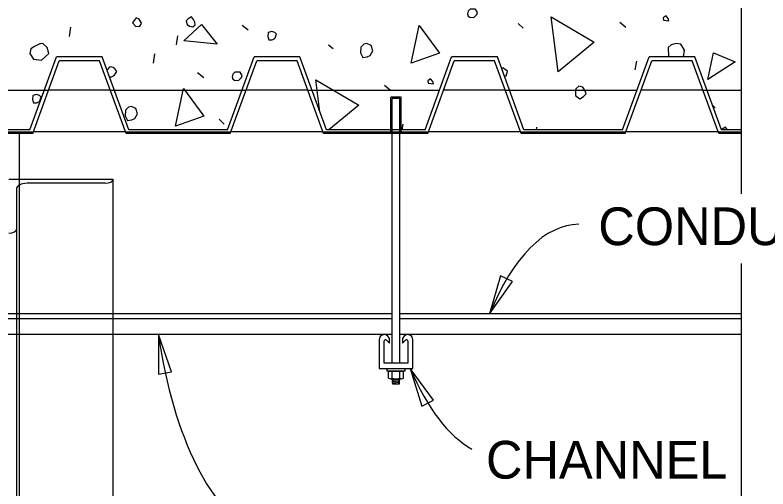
# Model space of a CAD drawing. Extents: x -1660015.2 to -1659984.9, y 2580594.2 to 2580616.7.
# Drawn here: x -1659997.457 to -1659994.444, y 2580601.617 to 2580603.515 of the extents above; entities that cross this region are included whole.
import ezdxf

# ---------------------------------------------------------------- set-up
doc = ezdxf.new("R2010")
doc.units = 0
for name, color, linetype in [('Default', 7, 'Continuous'), ('Miscellaneous', 7, 'Continuous'), ('PlotBorder_dp', 7, 'Continuous'), ('SheetLines_dp', 7, 'Continuous'), ('SteelGirder', 7, 'Continuous')]:
    doc.layers.add(name, color=color, linetype=linetype)

msp = doc.modelspace()

# ---------------------------------------------------------------- linework, layer by layer
at = {"layer": 'Default'}
for p, q in [((-1659997.8661, 2580603.2146), (-1659997.3226, 2580603.2146)), ((-1659997.0757, 2580603.2146), (-1659996.5322, 2580603.2146)), ((-1659996.2852, 2580603.2146), (-1659995.7583, 2580603.2146)), ((-1659995.4948, 2580603.2146), (-1659994.9679, 2580603.2146)), ((-1659994.7044, 2580603.2146), (-1659994.5491, 2580603.2146)), ((-1659997.8054, 2580603.0479), (-1659997.3833, 2580603.0479)), ((-1659997.015, 2580603.0479), (-1659996.5928, 2580603.0479)), ((-1659996.2246, 2580603.0479), (-1659996.1516, 2580603.0479)), ((-1659996.2246, 2580603.0479), (-1659995.8024, 2580603.0479)), ((-1659995.4341, 2580603.0479), (-1659995.3612, 2580603.0479)), ((-1659995.4341, 2580603.0479), (-1659995.012, 2580603.0479)), ((-1659994.6437, 2580603.0479), (-1659994.5707, 2580603.0479)), ((-1659994.6437, 2580603.0479), (-1659994.5491, 2580603.0479)), ((-1659997.4398, 2580602.8574), (-1659997.4398, 2580597.9633)), ((-1659997.0649, 2580602.3186), (-1659997.6586, 2580602.3186)), ((-1659995.9478, 2580602.3186), (-1659997.0649, 2580602.3186)), ((-1659994.5491, 2580602.3186), (-1659995.9166, 2580602.3186)), ((-1659997.0649, 2580602.2978), (-1659997.6586, 2580602.2978)), ((-1659995.9478, 2580602.2978), (-1659997.0649, 2580602.2978)), ((-1659994.5491, 2580602.2978), (-1659995.9166, 2580602.2978)), ((-1659997.0649, 2580602.2353), (-1659997.6586, 2580602.2353)), ((-1659995.9478, 2580602.2353), (-1659997.0649, 2580602.2353)), ((-1659995.9583, 2580602.2194), (-1659995.9605, 2580602.2237)), ((-1659994.5491, 2580602.2353), (-1659995.9166, 2580602.2353)), ((-1659995.904, 2580602.2237), (-1659995.9061, 2580602.2194)), ((-1659995.9999, 2580602.2145), (-1659995.9999, 2580602.0999)), ((-1659995.9791, 2580602.1207), (-1659995.9791, 2580602.2097)), ((-1659995.9703, 2580602.2134), (-1659995.9583, 2580602.2015)), ((-1659995.9583, 2580602.2015), (-1659995.9583, 2580602.2194)), ((-1659995.9061, 2580602.2194), (-1659995.9061, 2580602.2015)), ((-1659995.9061, 2580602.2015), (-1659995.8942, 2580602.2134)), ((-1659995.8853, 2580602.2097), (-1659995.8853, 2580602.1207)), ((-1659995.8645, 2580602.0999), (-1659995.8645, 2580602.2145)), ((-1659995.8853, 2580602.1207), (-1659995.9791, 2580602.1207)), ((-1659995.9999, 2580602.0999), (-1659995.8645, 2580602.0999))]:
    msp.add_line(p, q, dxfattribs=at)
for centre, radius, start, end in [((-1659995.9791, 2580602.2145), 0.0208, 26.1794, 179.9999), ((-1659995.8853, 2580602.2145), 0.0208, 0.0001, 153.8206), ((-1659995.9739, 2580602.2097), 0.0052, 45, 180), ((-1659995.8905, 2580602.2097), 0.0052, 360, 135)]:
    msp.add_arc(centre, radius, start, end, dxfattribs=at)
at = {"layer": 'Miscellaneous'}
for p, q in [((-1659997.239, 2580603.4291), (-1659997.2336, 2580603.4668)), ((-1659996.5472, 2580603.4747), (-1659996.5239, 2580603.4551)), ((-1659995.4436, 2580603.4805), (-1659995.4233, 2580603.4627)), ((-1659995.0362, 2580603.4861), (-1659995.0129, 2580603.4665)), ((-1659996.8109, 2580603.3963), (-1659996.8049, 2580603.4315)), ((-1659996.2027, 2580603.3962), (-1659996.183, 2580603.3807)), ((-1659997.397, 2580603.0559), (-1659997.2908, 2580603.3477)), ((-1659997.1075, 2580603.3477), (-1659997.2908, 2580603.3477)), ((-1659997.0013, 2580603.0559), (-1659997.1075, 2580603.3477)), ((-1659996.9025, 2580603.3225), (-1659996.897, 2580603.3602)), ((-1659996.6065, 2580603.0559), (-1659996.5004, 2580603.3477)), ((-1659996.3171, 2580603.3477), (-1659996.5004, 2580603.3477)), ((-1659996.2109, 2580603.0559), (-1659996.3171, 2580603.3477)), ((-1659995.8161, 2580603.0559), (-1659995.7099, 2580603.3477)), ((-1659995.5266, 2580603.3477), (-1659995.7099, 2580603.3477)), ((-1659995.6986, 2580603.3501), (-1659995.6961, 2580603.3477)), ((-1659995.4204, 2580603.0559), (-1659995.5266, 2580603.3477)), ((-1659995.0257, 2580603.0559), (-1659994.9195, 2580603.3477)), ((-1659994.7362, 2580603.3477), (-1659994.9195, 2580603.3477)), ((-1659994.63, 2580603.0559), (-1659994.7362, 2580603.3477)), ((-1659997.3861, 2580603.0403), (-1659997.2799, 2580603.3321)), ((-1659997.1184, 2580603.3321), (-1659997.2799, 2580603.3321)), ((-1659997.0122, 2580603.0403), (-1659997.1184, 2580603.3321)), ((-1659996.5956, 2580603.0403), (-1659996.4894, 2580603.3321)), ((-1659996.328, 2580603.3321), (-1659996.4894, 2580603.3321)), ((-1659996.2218, 2580603.0403), (-1659996.328, 2580603.3321)), ((-1659995.8052, 2580603.0403), (-1659995.699, 2580603.3321)), ((-1659995.5375, 2580603.3321), (-1659995.699, 2580603.3321)), ((-1659995.4313, 2580603.0403), (-1659995.5375, 2580603.3321)), ((-1659995.0147, 2580603.0403), (-1659994.9086, 2580603.3321)), ((-1659994.9748, 2580603.2955), (-1659994.9687, 2580603.3308)), ((-1659994.7471, 2580603.3321), (-1659994.9086, 2580603.3321)), ((-1659994.6409, 2580603.0403), (-1659994.7471, 2580603.3321)), ((-1659996.7266, 2580603.2843), (-1659996.7008, 2580603.2653)), ((-1659995.978, 2580603.2338), (-1659995.9546, 2580603.2142)), ((-1659994.6657, 2580603.1542), (-1659994.6545, 2580603.1433)), ((-1659996.6404, 2580603.0977), (-1659996.6194, 2580603.0775)), ((-1659995.9075, 2580603.0559), (-1659995.9036, 2580603.0785)), ((-1659997.3861, 2580603.0403), (-1659997.8027, 2580603.0403)), ((-1659997.397, 2580603.0559), (-1659997.7917, 2580603.0559)), ((-1659996.5956, 2580603.0403), (-1659997.0122, 2580603.0403)), ((-1659996.6065, 2580603.0559), (-1659997.0013, 2580603.0559)), ((-1659995.8052, 2580603.0403), (-1659996.2218, 2580603.0403)), ((-1659995.8161, 2580603.0559), (-1659996.2109, 2580603.0559)), ((-1659995.0147, 2580603.0403), (-1659995.4313, 2580603.0403)), ((-1659995.0257, 2580603.0559), (-1659995.4204, 2580603.0559)), ((-1659995.3702, 2580603.0559), (-1659995.3688, 2580603.0658)), ((-1659994.5491, 2580603.0403), (-1659994.6409, 2580603.0403)), ((-1659994.5491, 2580603.0559), (-1659994.63, 2580603.0559))]:
    msp.add_line(p, q, dxfattribs=at)
for points in [[(-1659995.6431, 2580603.5099), (-1659995.6369, 2580603.5064), (-1659995.6211, 2580603.5054), (-1659995.6086, 2580603.5165), (-1659995.6057, 2580603.5251), (-1659995.6144, 2580603.5383), (-1659995.635, 2580603.5379), (-1659995.6434, 2580603.5305), (-1659995.6456, 2580603.5196), (-1659995.6431, 2580603.5099)], [(-1659996.9871, 2580603.4836), (-1659996.9729, 2580603.4693), (-1659996.9577, 2580603.4708), (-1659996.95, 2580603.4806), (-1659996.9513, 2580603.4855), (-1659996.96, 2580603.4987), (-1659996.9716, 2580603.5033), (-1659996.9793, 2580603.4935), (-1659996.9871, 2580603.4836)], [(-1659996.768, 2580603.4776), (-1659996.7582, 2580603.4699), (-1659996.7448, 2580603.4683), (-1659996.7365, 2580603.4757), (-1659996.7366, 2580603.486), (-1659996.7423, 2580603.4975), (-1659996.7504, 2580603.5082), (-1659996.7635, 2580603.4995), (-1659996.7719, 2580603.4921), (-1659996.768, 2580603.4776)], [(-1659995.2833, 2580603.2879), (-1659995.3113, 2580603.5082), (-1659995.1392, 2580603.4068), (-1659995.2833, 2580603.2879)], [(-1659994.8623, 2580603.4939), (-1659994.8411, 2580603.4919), (-1659994.8436, 2580603.5015), (-1659994.8517, 2580603.5123), (-1659994.8625, 2580603.5042), (-1659994.8623, 2580603.4939)], [(-1659996.7815, 2580603.4119), (-1659996.711, 2580603.4774), (-1659996.6484, 2580603.3984), (-1659996.7815, 2580603.4119)], [(-1659995.8721, 2580603.3217), (-1659995.8401, 2580603.4726), (-1659995.7588, 2580603.3624), (-1659995.8721, 2580603.3217)], [(-1659996.4446, 2580603.4297), (-1659996.4407, 2580603.4152), (-1659996.428, 2580603.416), (-1659996.4166, 2580603.4217), (-1659996.4108, 2580603.4388), (-1659996.4176, 2580603.4447), (-1659996.4292, 2580603.4494), (-1659996.4437, 2580603.4455), (-1659996.4446, 2580603.4297)], [(-1659997.3968, 2580603.3609), (-1659997.383, 2580603.3387), (-1659997.3508, 2580603.3344), (-1659997.3215, 2580603.3604), (-1659997.328, 2580603.3845), (-1659997.3453, 2580603.4006), (-1659997.358, 2580603.3998), (-1659997.3784, 2580603.3891), (-1659997.394, 2580603.3798), (-1659997.3968, 2580603.3609)], [(-1659996.0734, 2580603.3868), (-1659996.0748, 2580603.3632), (-1659996.0648, 2580603.3451), (-1659996.0472, 2580603.3472), (-1659996.0358, 2580603.3529), (-1659996.0252, 2580603.3713), (-1659996.031, 2580603.393), (-1659996.0487, 2580603.4012), (-1659996.0608, 2580603.398), (-1659996.0734, 2580603.3868)], [(-1659994.782, 2580603.3477), (-1659994.7784, 2580603.374), (-1659994.7928, 2580603.3987), (-1659994.8116, 2580603.4014), (-1659994.831, 2580603.3962), (-1659994.8435, 2580603.3851)], [(-1659994.8435, 2580603.3851), (-1659994.8424, 2580603.3477)], [(-1659994.6849, 2580603.2568), (-1659994.6618, 2580603.3639), (-1659994.5745, 2580603.3277), (-1659994.6849, 2580603.2568)], [(-1659997.0787, 2580603.2686), (-1659997.0738, 2580603.2663), (-1659997.0599, 2580603.2726), (-1659997.0487, 2580603.2886), (-1659997.0567, 2580603.2993), (-1659997.0635, 2580603.3053), (-1659997.0744, 2580603.3075), (-1659997.0793, 2580603.3062), (-1659997.0886, 2580603.2957)], [(-1659996.5848, 2580603.2575), (-1659996.5787, 2580603.254), (-1659996.5629, 2580603.2531), (-1659996.5504, 2580603.2642), (-1659996.5475, 2580603.2727), (-1659996.5562, 2580603.2859), (-1659996.5768, 2580603.2856), (-1659996.5852, 2580603.2782), (-1659996.5874, 2580603.2672), (-1659996.5848, 2580603.2575)], [(-1659995.4981, 2580603.2692), (-1659995.4911, 2580603.2711), (-1659995.4859, 2580603.2906), (-1659995.505, 2580603.3036), (-1659995.5092, 2580603.2998)], [(-1659996.2367, 2580603.127), (-1659996.2531, 2580603.2558), (-1659996.081, 2580603.1544), (-1659996.2005, 2580603.0559)], [(-1659995.8041, 2580603.2416), (-1659995.7828, 2580603.2395), (-1659995.7854, 2580603.2492), (-1659995.7935, 2580603.2599), (-1659995.8043, 2580603.2519), (-1659995.8041, 2580603.2416)], [(-1659996.8139, 2580603.0693), (-1659996.7819, 2580603.2203), (-1659996.7006, 2580603.1101), (-1659996.8139, 2580603.0693)], [(-1659995.2135, 2580603.2109), (-1659995.2138, 2580603.1927), (-1659995.1972, 2580603.179), (-1659995.1816, 2580603.1884), (-1659995.1715, 2580603.1988), (-1659995.1747, 2580603.2109), (-1659995.1841, 2580603.2265), (-1659995.2005, 2580603.2299), (-1659995.213, 2580603.2188), (-1659995.2135, 2580603.2109)], [(-1659997.3864, 2580603.1774), (-1659997.3825, 2580603.1629), (-1659997.3698, 2580603.1637), (-1659997.3584, 2580603.1693), (-1659997.3526, 2580603.1864), (-1659997.3593, 2580603.1924), (-1659997.3709, 2580603.197), (-1659997.3854, 2580603.1931), (-1659997.3864, 2580603.1774)], [(-1659997.0151, 2580603.1345), (-1659997.0166, 2580603.1108), (-1659997.0066, 2580603.0928), (-1659996.989, 2580603.0949), (-1659996.9776, 2580603.1005), (-1659996.967, 2580603.1189), (-1659996.9728, 2580603.1406), (-1659996.9905, 2580603.1488), (-1659997.0026, 2580603.1456), (-1659997.0151, 2580603.1345)], [(-1659994.6053, 2580603.0559), (-1659994.6132, 2580603.0663), (-1659994.6264, 2580603.0576), (-1659994.6283, 2580603.0559)]]:
    msp.add_lwpolyline(points, dxfattribs=at)
at = {"layer": 'SheetLines_dp'}
for points in [[(-1659994.5491, 2580602.799), (-1659994.5491, 2580604.252)], [(-1659994.5491, 2580596.5919), (-1659994.5491, 2580600.3516), (-1659994.6266, 2580600.3516), (-1659994.5491, 2580600.3853), (-1659994.4716, 2580600.4191), (-1659994.5491, 2580600.4191), (-1659994.5491, 2580602.5196)]]:
    msp.add_lwpolyline(points, dxfattribs=at)
for points in [[(-1659995.5578, 2580602.3186), (-1659995.4665, 2580602.448), (-1659995.5142, 2580602.4709)], [(-1659996.8829, 2580602.2353), (-1659996.8828, 2580602.0769), (-1659996.8306, 2580602.0858)], [(-1659995.8753, 2580602.0999), (-1659995.829, 2580601.9484), (-1659995.7817, 2580601.9721)]]:
    msp.add_lwpolyline(points, close=True, dxfattribs=at)
for centre, start_param, end_param in [((-1659995.1923, 2580601.4957), 3.141637, 3.939024), ((-1659996.4069, 2580602.6059), 5.02876, 6.111261), ((-1659995.5206, 2580602.9277), 5.486066, 6.052475)]:
    msp.add_ellipse(centre, major_axis=(0.0076, -1.1813), ratio=0.426092, start_param=start_param, end_param=end_param, dxfattribs=at)
at = {"layer": 'SteelGirder'}
for p, q in [((-1659997.0757, 2580603.2146), (-1659997.3226, 2580603.2146)), ((-1659996.2852, 2580603.2146), (-1659996.5322, 2580603.2146)), ((-1659995.4948, 2580603.2146), (-1659995.7417, 2580603.2146)), ((-1659994.7044, 2580603.2146), (-1659994.9513, 2580603.2146)), ((-1659995.9114, 2580603.1861), (-1659995.953, 2580603.1861)), ((-1659995.953, 2580603.0403), (-1659995.953, 2580603.1861)), ((-1659995.9478, 2580602.1207), (-1659995.9478, 2580603.1809)), ((-1659995.9166, 2580603.1809), (-1659995.9478, 2580603.1809)), ((-1659995.9166, 2580602.1207), (-1659995.9166, 2580603.1809)), ((-1659995.9114, 2580603.0403), (-1659995.9114, 2580603.1861)), ((-1659997.4398, 2580603.0479), (-1659997.4398, 2580602.8574)), ((-1659997.015, 2580603.0479), (-1659997.3833, 2580603.0479)), ((-1659996.2246, 2580603.0479), (-1659996.5928, 2580603.0479)), ((-1659995.4341, 2580603.0479), (-1659995.8024, 2580603.0479)), ((-1659994.6437, 2580603.0479), (-1659995.012, 2580603.0479)), ((-1659997.4815, 2580602.8574), (-1659997.0649, 2580602.8574)), ((-1659997.0649, 2580602.8574), (-1659997.0649, 2580597.9867)), ((-1659997.0961, 2580602.8413), (-1659997.4086, 2580602.8413)), ((-1659997.4503, 2580602.8197), (-1659997.4503, 2580602.6579)), ((-1659997.4503, 2580602.6579), (-1659997.4503, 2580597.787)), ((-1659995.9623, 2580602.0604), (-1659995.9623, 2580602.0888)), ((-1659995.9623, 2580602.0888), (-1659995.9022, 2580602.0888)), ((-1659995.9473, 2580602.0604), (-1659995.9473, 2580602.0888)), ((-1659995.9172, 2580602.0604), (-1659995.9172, 2580602.0888)), ((-1659995.9022, 2580602.0604), (-1659995.9022, 2580602.0888)), ((-1659995.9548, 2580602.0582), (-1659995.9097, 2580602.0582)), ((-1659995.9479, 2580602.0576), (-1659995.9413, 2580602.0582)), ((-1659995.9479, 2580602.0576), (-1659995.9469, 2580602.0582)), ((-1659995.9427, 2580602.0554), (-1659995.9479, 2580602.0576)), ((-1659995.9479, 2580602.0524), (-1659995.9427, 2580602.0554)), ((-1659995.9479, 2580602.0524), (-1659995.9167, 2580602.0551)), ((-1659995.9427, 2580602.0502), (-1659995.9479, 2580602.0524)), ((-1659995.9479, 2580602.0472), (-1659995.9427, 2580602.0502)), ((-1659995.9479, 2580602.0472), (-1659995.9167, 2580602.0499)), ((-1659995.9427, 2580602.0451), (-1659995.9479, 2580602.0472)), ((-1659995.9479, 2580602.042), (-1659995.9427, 2580602.0451)), ((-1659995.9479, 2580602.042), (-1659995.9167, 2580602.0447)), ((-1659995.9219, 2580602.0572), (-1659995.9203, 2580602.0582)), ((-1659995.9167, 2580602.0551), (-1659995.9219, 2580602.0572)), ((-1659995.9219, 2580602.052), (-1659995.9167, 2580602.0551)), ((-1659995.9167, 2580602.0499), (-1659995.9219, 2580602.052)), ((-1659995.9219, 2580602.0469), (-1659995.9167, 2580602.0499)), ((-1659995.9167, 2580602.0447), (-1659995.9219, 2580602.0469)), ((-1659995.9219, 2580602.0417), (-1659995.9167, 2580602.0447)), ((-1659995.9427, 2580602.0398), (-1659995.9479, 2580602.042)), ((-1659995.9461, 2580602.0379), (-1659995.9427, 2580602.0398)), ((-1659995.9461, 2580602.0379), (-1659995.9195, 2580602.0379)), ((-1659995.936, 2580602.0379), (-1659995.9167, 2580602.0395)), ((-1659995.9167, 2580602.0395), (-1659995.9219, 2580602.0417)), ((-1659995.9195, 2580602.0379), (-1659995.9167, 2580602.0395))]:
    msp.add_line(p, q, dxfattribs=at)
msp.add_lwpolyline([(-1659995.897, 2580602.0999), (-1659995.897, 2580602.0888), (-1659995.9675, 2580602.0888), (-1659995.9675, 2580602.0999)], close=True, dxfattribs=at)
for centre, radius, start, end in [((-1659995.9548, 2580602.072), 0.0138, 236.9791, 303.0209), ((-1659995.9323, 2580602.11), 0.0519, 253.1396, 286.8604), ((-1659995.9097, 2580602.072), 0.0138, 236.9791, 303.0209)]:
    msp.add_arc(centre, radius, start, end, dxfattribs=at)
for centre, major_axis in [((-1659997.0961, 2580602.8574), (0.0313, 0)), ((-1659997.4086, 2580602.8197), (-0.0417, 0)), ((-1659997.4815, 2580602.6579), (0.0312, 0))]:
    msp.add_ellipse(centre, major_axis=major_axis, ratio=0.5176, start_param=4.712389, end_param=6.283185, dxfattribs=at)

# ---------------------------------------------------------------- texts
at = {"layer": 'PlotBorder_dp'}
for s, p in [('CONDUIT (480V)', (-1659995.1227, 2580602.5934)), ('CHANNEL', (-1659995.5721, 2580601.6583))]:
    msp.add_text(s, height=0.1512, dxfattribs=at).set_placement(p)

doc.saveas('drawing.dxf')
